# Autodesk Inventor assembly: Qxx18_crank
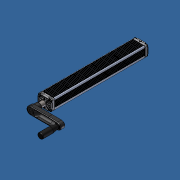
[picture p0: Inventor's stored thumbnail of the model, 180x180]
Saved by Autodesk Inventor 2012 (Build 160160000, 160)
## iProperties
Created: 2013-10
Part Number: Qxx18_crank
Document SubType Name: Assembly
Designer: Admin
Translation Standard: STEP AP214IS
FileName: Qxx18_crank.STEP
PreProcessor: SolidWorks 2009
PostProcessor: Build: 160, Release: 2012 RTM - Date: Tue 03/01/2011
Sent Units: millimeter
Uncertainty: 1e-05
Author: Admin
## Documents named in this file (4)
- C:\Andys Backup Data\ANDY'S INVENTOR\INVENTOR LIBRARIES\PARTS LIBRARY\HYDRAULIC VERTICAL ADJUSTMENT\27.9001Telescoping Twin Leg System\SUBCOMPONENTS\Qxx18_crank pump\Qxx18_crank.iam
- C:\Andys Backup Data\ANDY'S INVENTOR\INVENTOR LIBRARIES\PARTS LIBRARY\HYDRAULIC VERTICAL ADJUSTMENT\27.9001Telescoping Twin Leg System\SUBCOMPONENTS\Qxx18_crank pump\D44-00039 130mm AL Crank.iam
- C:\Andys Backup Data\ANDY'S INVENTOR\INVENTOR LIBRARIES\PARTS LIBRARY\HYDRAULIC VERTICAL ADJUSTMENT\27.9001Telescoping Twin Leg System\SUBCOMPONENTS\Qxx18_crank pump\697-00124 M5X50 FLATHEAD CAP SCREW.ipt
- C:\Andys Backup Data\ANDY'S INVENTOR\INVENTOR LIBRARIES\PARTS LIBRARY\HYDRAULIC VERTICAL ADJUSTMENT\27.9001Telescoping Twin Leg System\SUBCOMPONENTS\Qxx18_crank pump\S43-0008 QUAD PUMP WITH SPLINED SHAFT.iam
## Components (3 placed, 3 different names)
1. D44-00039 130mm AL Crank:1 [sub-assembly]
2. 697-00124 M5X50 FLATHEAD CAP SCREW:1
3. S43-0008 QUAD PUMP WITH SPLINED SHAFT:1 [sub-assembly]
